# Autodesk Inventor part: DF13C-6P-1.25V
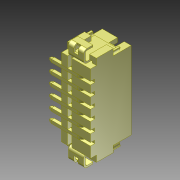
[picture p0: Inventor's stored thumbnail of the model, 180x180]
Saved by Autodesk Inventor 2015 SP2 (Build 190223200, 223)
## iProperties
Created: 2015-10
Part Number: DF13C-6P-1.25V
Material: Allgemein
Document SubType Name: Modeling
Designer: rYan
Density: 1 g/cm^3
Appearance: Vorgabe
Author: rYan
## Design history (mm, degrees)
node "DF13C-6P-1.25VÈª.ipt1"
node "Volumenkörper1"
node "Basis1"
